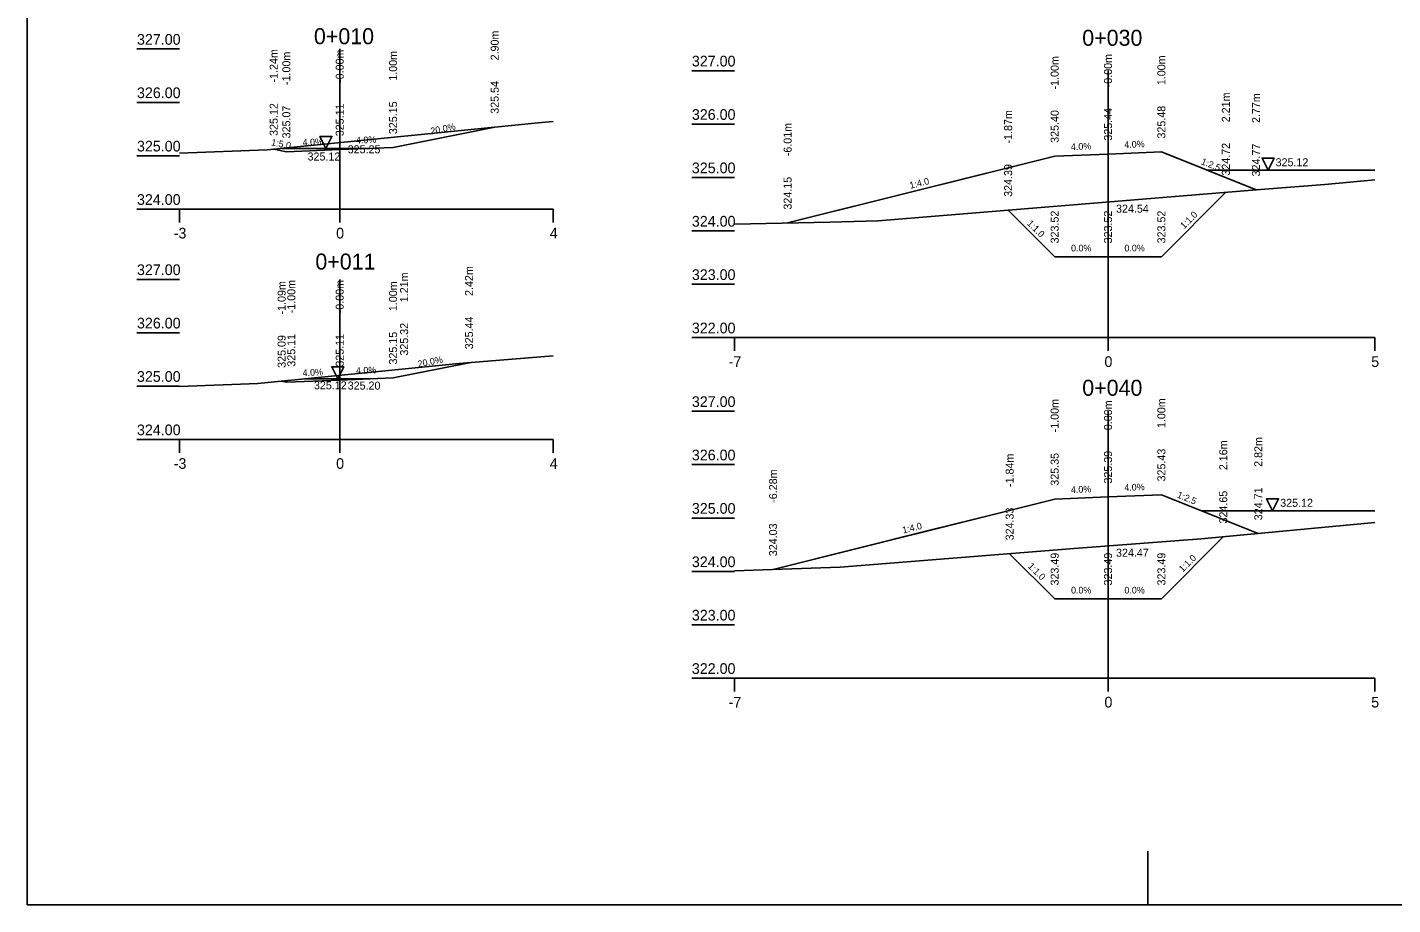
# Model space of a CAD drawing. Extents: x -560313 to -560271, y -1162459.6 to -1162429.9.
# Drawn here: x -560313.01 to -560287.42, y -1162459.61 to -1162443.18 of the extents above; entities that cross this region are included whole.
import ezdxf

# ---------------------------------------------------------------- set-up
doc = ezdxf.new("R2010")
doc.units = 0
for name, color, linetype in [('16', 7, 'Continuous'), ('21', 7, 'Continuous'), ('28', 7, 'Continuous'), ('59', 7, 'Continuous'), ('Body pricny rez', 7, 'Continuous'), ('Popis pricneho profilu', 7, 'Continuous')]:
    doc.layers.add(name, color=color, linetype=linetype)

msp = doc.modelspace()

# ---------------------------------------------------------------- linework, layer by layer
for p, q in [((-560313.013, -1162429.91), (-560313.013, -1162459.61)), ((-560292.013, -1162459.61), (-560292.013, -1162458.61)), ((-560313.013, -1162459.61), (-560271.013, -1162459.61))]:
    msp.add_line(p, q)
for points in [[(-560310.158, -1162445.533), (-560308.518, -1162445.471), (-560303.375, -1162444.958), (-560303.158, -1162444.94)], [(-560308.395, -1162445.459), (-560308.158, -1162445.506), (-560307.158, -1162445.466), (-560306.158, -1162445.426), (-560304.253, -1162445.045)], [(-560306.158, -1162445.426), (-560304.253, -1162445.045)], [(-560308.158, -1162445.506), (-560308.395, -1162445.459)], [(-560308.243, -1162445.444), (-560306.592, -1162445.444)], [(-560307.158, -1162445.466), (-560308.158, -1162445.506)], [(-560307.158, -1162445.466), (-560306.158, -1162445.426)], [(-560298.763, -1162446.84), (-560294.977, -1162445.893), (-560293.758, -1162445.589), (-560292.758, -1162445.549), (-560291.758, -1162445.509), (-560289.984, -1162446.218)], [(-560292.758, -1162445.549), (-560291.758, -1162445.509)], [(-560291.758, -1162445.509), (-560289.984, -1162446.218)], [(-560293.758, -1162445.589), (-560298.763, -1162446.84)], [(-560292.758, -1162445.549), (-560293.758, -1162445.589)], [(-560299.758, -1162446.862), (-560297.97, -1162446.823), (-560297.074, -1162446.802), (-560297.064, -1162446.802), (-560289.901, -1162446.211), (-560288.694, -1162446.122), (-560287.758, -1162446.035)], [(-560290.902, -1162445.851), (-560287.758, -1162445.851)], [(-560294.63, -1162446.601), (-560293.758, -1162447.473), (-560292.758, -1162447.473), (-560291.758, -1162447.473), (-560290.55, -1162446.265)], [(-560291.758, -1162447.473), (-560290.55, -1162446.265)], [(-560293.758, -1162447.473), (-560294.63, -1162446.601)], [(-560292.758, -1162447.473), (-560293.758, -1162447.473)], [(-560292.758, -1162447.473), (-560291.758, -1162447.473)], [(-560310.158, -1162449.904), (-560308.69, -1162449.848), (-560304.928, -1162449.473), (-560303.158, -1162449.328)], [(-560306.158, -1162449.742), (-560304.734, -1162449.457)], [(-560308.158, -1162449.822), (-560308.246, -1162449.804)], [(-560307.158, -1162449.782), (-560308.158, -1162449.822)], [(-560307.797, -1162449.759), (-560306.592, -1162449.759)], [(-560307.158, -1162449.782), (-560306.158, -1162449.742)], [(-560299.036, -1162453.332), (-560297.54, -1162452.958), (-560296.071, -1162452.591), (-560294.904, -1162452.299), (-560293.758, -1162452.012), (-560292.758, -1162451.972), (-560291.758, -1162451.932), (-560289.942, -1162452.659)], [(-560293.758, -1162452.012), (-560299.036, -1162453.332)], [(-560292.758, -1162451.972), (-560293.758, -1162452.012)], [(-560292.758, -1162451.972), (-560291.758, -1162451.932)], [(-560291.758, -1162451.932), (-560289.942, -1162452.659)], [(-560291.015, -1162452.23), (-560287.758, -1162452.23)], [(-560299.758, -1162453.359), (-560298.863, -1162453.326), (-560297.777, -1162453.288), (-560293.39, -1162452.94), (-560291.013, -1162452.76), (-560287.888, -1162452.465), (-560287.758, -1162452.452)], [(-560294.602, -1162453.036), (-560293.758, -1162453.881), (-560292.758, -1162453.881), (-560291.758, -1162453.881), (-560290.598, -1162452.72)], [(-560291.758, -1162453.881), (-560290.598, -1162452.72)], [(-560293.758, -1162453.881), (-560294.602, -1162453.036)], [(-560292.758, -1162453.881), (-560293.758, -1162453.881)], [(-560292.758, -1162453.881), (-560291.758, -1162453.881)]]:
    msp.add_lwpolyline(points)
for points in [[(-560307.418, -1162445.444), (-560307.53, -1162445.219), (-560307.305, -1162445.219)], [(-560289.759, -1162445.851), (-560289.871, -1162445.626), (-560289.646, -1162445.626)], [(-560307.194, -1162449.759), (-560307.307, -1162449.534), (-560307.082, -1162449.534)], [(-560289.674, -1162452.23), (-560289.786, -1162452.005), (-560289.561, -1162452.005)]]:
    msp.add_lwpolyline(points, close=True)
at = {"layer": '16'}
for p, q in [((-560310.158, -1162446.581), (-560303.158, -1162446.581)), ((-560299.758, -1162448.988), (-560287.758, -1162448.988)), ((-560310.158, -1162450.896), (-560303.158, -1162450.896)), ((-560299.758, -1162455.367), (-560287.758, -1162455.367))]:
    msp.add_line(p, q, dxfattribs=at)
at = {"layer": '21'}
for p, q in [((-560310.958, -1162443.581), (-560310.158, -1162443.581)), ((-560300.558, -1162443.988), (-560299.758, -1162443.988)), ((-560310.958, -1162444.581), (-560310.158, -1162444.581)), ((-560300.558, -1162444.988), (-560299.758, -1162444.988)), ((-560310.958, -1162445.581), (-560310.158, -1162445.581)), ((-560300.558, -1162445.988), (-560299.758, -1162445.988)), ((-560310.958, -1162446.581), (-560310.158, -1162446.581)), ((-560300.558, -1162446.988), (-560299.758, -1162446.988)), ((-560310.958, -1162447.896), (-560310.158, -1162447.896)), ((-560300.558, -1162447.988), (-560299.758, -1162447.988)), ((-560310.958, -1162448.896), (-560310.158, -1162448.896)), ((-560300.558, -1162448.988), (-560299.758, -1162448.988)), ((-560310.958, -1162449.896), (-560310.158, -1162449.896)), ((-560300.558, -1162450.367), (-560299.758, -1162450.367)), ((-560310.958, -1162450.896), (-560310.158, -1162450.896)), ((-560300.558, -1162451.367), (-560299.758, -1162451.367)), ((-560300.558, -1162452.367), (-560299.758, -1162452.367)), ((-560300.558, -1162453.367), (-560299.758, -1162453.367)), ((-560300.558, -1162454.367), (-560299.758, -1162454.367)), ((-560300.558, -1162455.367), (-560299.758, -1162455.367))]:
    msp.add_line(p, q, dxfattribs=at)
at = {"layer": '28'}
for p, q in [((-560307.158, -1162443.581), (-560307.158, -1162446.581)), ((-560292.758, -1162443.988), (-560292.758, -1162448.988)), ((-560307.158, -1162447.896), (-560307.158, -1162450.896)), ((-560292.758, -1162450.367), (-560292.758, -1162455.367))]:
    msp.add_line(p, q, dxfattribs=at)
at = {"layer": '59'}
for p, q in [((-560310.158, -1162446.831), (-560310.158, -1162446.581)), ((-560307.158, -1162446.831), (-560307.158, -1162446.581)), ((-560303.158, -1162446.831), (-560303.158, -1162446.581)), ((-560299.758, -1162449.238), (-560299.758, -1162448.988)), ((-560292.758, -1162449.238), (-560292.758, -1162448.988)), ((-560287.758, -1162449.238), (-560287.758, -1162448.988)), ((-560310.158, -1162451.146), (-560310.158, -1162450.896)), ((-560307.158, -1162451.146), (-560307.158, -1162450.896)), ((-560303.158, -1162451.146), (-560303.158, -1162450.896)), ((-560299.758, -1162455.617), (-560299.758, -1162455.367)), ((-560292.758, -1162455.617), (-560292.758, -1162455.367)), ((-560287.758, -1162455.617), (-560287.758, -1162455.367))]:
    msp.add_line(p, q, dxfattribs=at)

# ---------------------------------------------------------------- texts
for s, height, p in [('0+010', 0.3, (-560307.641, -1162443.492)), ('0+030', 0.3, (-560293.241, -1162443.521)), ('325.12', 0.15, (-560307.76, -1162445.67)), ('325.12', 0.15, (-560289.617, -1162445.778)), ('0+011', 0.3, (-560307.614, -1162447.713)), ('325.12', 0.15, (-560307.641, -1162449.956)), ('0+040', 0.3, (-560293.241, -1162450.077)), ('325.12', 0.15, (-560289.531, -1162452.157))]:
    msp.add_text(s, height=height).set_placement(p)
for s, rotation, p in [('1:5.0', 348.6901, (-560308.45, -1162445.384)), ('1:2.5', 338.1986, (-560291.025, -1162445.735)), ('1:4.0', 14.0362, (-560296.46, -1162446.2)), ('1:1.0', 315, (-560294.284, -1162446.859)), ('1:1.0', 45, (-560291.332, -1162446.959)), ('1:2.5', 338.1986, (-560291.475, -1162451.981)), ('1:4.0', 14.0362, (-560296.596, -1162452.658)), ('1:1.0', 45, (-560291.356, -1162453.391)), ('1:1.0', 315, (-560294.27, -1162453.28))]:
    msp.add_text(s, height=0.125, rotation=rotation).set_placement(p)
at = {"layer": '16'}
for s, rotation, p in [('20.0%', 11.3099, (-560305.443, -1162445.183)), ('4.0%', 2.2906, (-560307.851, -1162445.394)), ('4.0%', 2.2906, (-560306.851, -1162445.354)), ('4.0%', 2.2906, (-560293.451, -1162445.476)), ('4.0%', 2.2906, (-560292.451, -1162445.436)), ('20.0%', 11.3099, (-560305.683, -1162449.547)), ('4.0%', 2.2906, (-560307.851, -1162449.709)), ('4.0%', 2.2906, (-560306.851, -1162449.669)), ('4.0%', 2.2906, (-560293.451, -1162451.9)), ('4.0%', 2.2906, (-560292.451, -1162451.86))]:
    msp.add_text(s, height=0.125, rotation=rotation, dxfattribs=at).set_placement(p)
for p in [(-560293.451, -1162447.373), (-560292.451, -1162447.373), (-560293.451, -1162453.781), (-560292.451, -1162453.781)]:
    msp.add_text('0.0%', height=0.125, dxfattribs=at).set_placement(p)
at = {"layer": '21'}
for s, p in [('327.00', (-560310.958, -1162443.501)), ('327.00', (-560300.558, -1162443.908)), ('326.00', (-560310.958, -1162444.501)), ('326.00', (-560300.558, -1162444.908)), ('325.00', (-560310.958, -1162445.501)), ('325.00', (-560300.558, -1162445.908)), ('324.00', (-560310.958, -1162446.501)), ('324.00', (-560300.558, -1162446.908)), ('-3', (-560310.269, -1162447.131)), ('0', (-560307.225, -1162447.131)), ('4', (-560303.221, -1162447.131)), ('327.00', (-560310.958, -1162447.816)), ('323.00', (-560300.558, -1162447.908)), ('326.00', (-560310.958, -1162448.816)), ('322.00', (-560300.558, -1162448.908)), ('-7', (-560299.869, -1162449.538)), ('0', (-560292.825, -1162449.538)), ('5', (-560287.825, -1162449.538)), ('325.00', (-560310.958, -1162449.816)), ('327.00', (-560300.558, -1162450.287)), ('324.00', (-560310.958, -1162450.816)), ('326.00', (-560300.558, -1162451.287)), ('-3', (-560310.269, -1162451.446)), ('0', (-560307.225, -1162451.446)), ('4', (-560303.221, -1162451.446)), ('325.00', (-560300.558, -1162452.287)), ('324.00', (-560300.558, -1162453.287)), ('323.00', (-560300.558, -1162454.287)), ('322.00', (-560300.558, -1162455.287)), ('-7', (-560299.869, -1162455.917)), ('0', (-560292.825, -1162455.917)), ('5', (-560287.825, -1162455.917))]:
    msp.add_text(s, height=0.2, dxfattribs=at).set_placement(p)
at = {"layer": '59'}
for s, p in [('325.25', (-560307.008, -1162445.535)), ('324.54', (-560292.608, -1162446.647)), ('325.20', (-560307.008, -1162449.961)), ('324.47', (-560292.608, -1162453.092))]:
    msp.add_text(s, height=0.15, dxfattribs=at).set_placement(p)
at = {"layer": 'Body pricny rez'}
for p in [(-560304.254, -1162445.046), (-560308.395, -1162445.459), (-560308.158, -1162445.507), (-560307.158, -1162445.467), (-560306.158, -1162445.427), (-560291.758, -1162445.509), (-560293.758, -1162445.589), (-560292.758, -1162445.549), (-560290.55, -1162446.265), (-560289.984, -1162446.219), (-560294.63, -1162446.602), (-560298.764, -1162446.841), (-560293.758, -1162447.474), (-560292.758, -1162447.474), (-560291.758, -1162447.474), (-560305.951, -1162449.575), (-560304.734, -1162449.457), (-560308.247, -1162449.805), (-560308.247, -1162449.805), (-560308.158, -1162449.822), (-560307.158, -1162449.782), (-560307.158, -1162449.782), (-560293.758, -1162452.013), (-560292.758, -1162451.973), (-560291.758, -1162451.933), (-560289.943, -1162452.659), (-560290.598, -1162452.721), (-560294.603, -1162453.037), (-560299.037, -1162453.332), (-560293.758, -1162453.881), (-560292.758, -1162453.881), (-560291.758, -1162453.881)]:
    msp.add_text('+', height=0.001, dxfattribs=at).set_placement(p)
at = {"layer": 'Popis pricneho profilu'}
for s, p in [('2.90m', (-560304.178, -1162443.795)), ('-1.24m', (-560308.32, -1162444.209)), ('-1.00m', (-560308.083, -1162444.256)), ('-0.00m', (-560307.083, -1162444.216)), ('1.00m', (-560306.083, -1162444.176)), ('-1.00m', (-560293.683, -1162444.339)), ('-0.00m', (-560292.683, -1162444.299)), ('1.00m', (-560291.683, -1162444.259)), ('325.54', (-560304.178, -1162444.795)), ('2.21m', (-560290.475, -1162444.954)), ('2.77m', (-560289.909, -1162444.968)), ('325.12', (-560308.32, -1162445.209)), ('325.07', (-560308.083, -1162445.256)), ('325.11', (-560307.083, -1162445.216)), ('325.15', (-560306.083, -1162445.176)), ('-1.87m', (-560294.555, -1162445.351)), ('325.40', (-560293.683, -1162445.339)), ('325.44', (-560292.683, -1162445.299)), ('325.48', (-560291.683, -1162445.259)), ('-6.01m', (-560298.688, -1162445.59)), ('324.72', (-560290.475, -1162445.954)), ('324.77', (-560289.909, -1162445.968)), ('324.39', (-560294.555, -1162446.351)), ('324.15', (-560298.688, -1162446.59)), ('323.52', (-560293.683, -1162447.223)), ('323.52', (-560292.683, -1162447.223)), ('323.52', (-560291.683, -1162447.223)), ('1.21m', (-560305.876, -1162448.325)), ('2.42m', (-560304.659, -1162448.207)), ('-1.09m', (-560308.171, -1162448.554)), ('-1.00m', (-560307.99, -1162448.532)), ('-0.00m', (-560307.083, -1162448.532)), ('-0.00m', (-560307.083, -1162448.532)), ('1.00m', (-560306.083, -1162448.492)), ('325.44', (-560304.659, -1162449.207)), ('325.32', (-560305.876, -1162449.325)), ('325.09', (-560308.171, -1162449.554)), ('325.11', (-560307.99, -1162449.532)), ('325.11', (-560307.083, -1162449.532)), ('325.11', (-560307.083, -1162449.532)), ('325.15', (-560306.083, -1162449.492)), ('-1.00m', (-560293.683, -1162450.762)), ('0.00m', (-560292.683, -1162450.722)), ('1.00m', (-560291.683, -1162450.682)), ('2.82m', (-560289.867, -1162451.409)), ('325.35', (-560293.683, -1162451.762)), ('325.39', (-560292.683, -1162451.722)), ('325.43', (-560291.683, -1162451.682)), ('2.16m', (-560290.523, -1162451.47)), ('-1.84m', (-560294.527, -1162451.786)), ('-6.28m', (-560298.961, -1162452.082)), ('324.65', (-560290.523, -1162452.47)), ('324.71', (-560289.867, -1162452.409)), ('324.33', (-560294.527, -1162452.786)), ('324.03', (-560298.961, -1162453.082)), ('323.49', (-560293.683, -1162453.631)), ('323.49', (-560292.683, -1162453.631)), ('323.49', (-560291.683, -1162453.631))]:
    msp.add_text(s, height=0.15, rotation=90, dxfattribs=at).set_placement(p)

doc.saveas('drawing.dxf')
